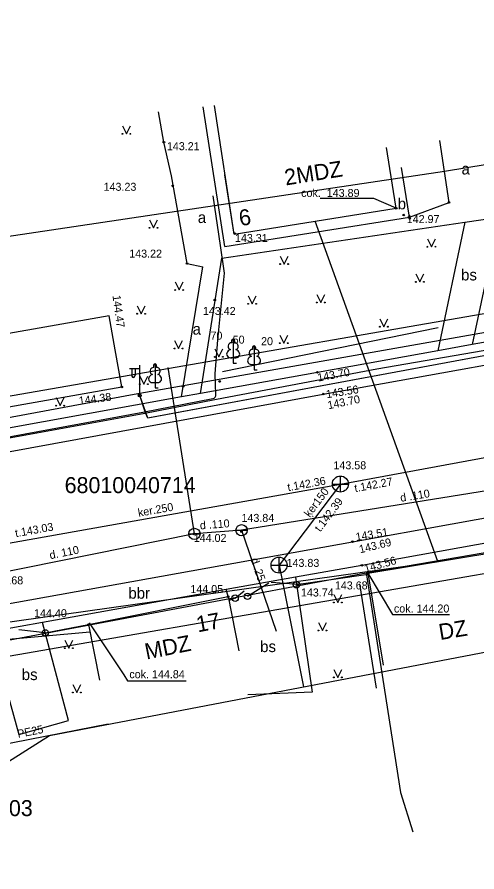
# Model space of a CAD drawing. Extents: x 728492 to 729038, y 272968 to 273171.
# Drawn here: x 728700.1 to 728728.8, y 273058.4 to 273111.8 of the extents above; entities that cross this region are included whole.
import ezdxf

# ---------------------------------------------------------------- set-up
doc = ezdxf.new("R2010")
doc.units = 0
for name, color, linetype in [('APGR_SARK_####_####_#', 7, 'Continuous'), ('APGS_ACRL_####_####_#', 7, 'Continuous'), ('APGS_ELEM_####_####_#', 7, 'Continuous'), ('APGS_VADP_ZSPR_####_I', 7, 'Continuous'), ('BUVE_BDET_####_####_#', 7, 'Continuous'), ('BUVE_BDET_####_TKST_#', 7, 'Continuous'), ('BUVE_EKAS_####_####_#', 7, 'Continuous'), ('BUVE_EKAS_ADRS_TKST_#', 7, 'Continuous'), ('BUVE_EKAS_RAKS_TKST_#', 7, 'Continuous'), ('CELI_CAPM_####_####_#', 7, 'Continuous'), ('CELI_CMAL_####_####_#', 7, 'Continuous'), ('CELI_CSEG_####_TKST_#', 7, 'Continuous'), ('CELI_SEGL_####_####_#', 7, 'Continuous'), ('ELEK_VADP_ZSPR_####_I', 7, 'Continuous'), ('NORB_ELEM_####_####_#', 7, 'Continuous'), ('NORB_ZOGS_BARJ_####_#', 7, 'Continuous'), ('NORB_ZOGS_KOKA_####_#', 7, 'Continuous'), ('RAMI_UZMR_####_####_#', 7, 'Continuous'), ('RELJ_AATZ_####_TKST_#', 7, 'Continuous'), ('RELJ_ELEM_####_####_#', 7, 'Continuous'), ('ROBZ_KADS_####_TKST_#', 7, 'Continuous'), ('ROBZ_UZMR_####_####_#', 7, 'Continuous'), ('SAKT_STUT_####_####_#', 7, 'Continuous'), ('SAKT_VADV_KLIN_####_#', 7, 'Continuous'), ('SKAN_ELEM_####_####_#', 7, 'Continuous'), ('SKAN_VADP_PAST_####_#', 7, 'Continuous'), ('SKAN_VADP_PAST_TKST_#', 7, 'Continuous'), ('TERT_DIAM_####_TKST_#', 7, 'Continuous'), ('TERT_DZOG_####_####_#', 7, 'Continuous'), ('TERT_ELEM_####_####_#', 7, 'Continuous'), ('TERT_KRND_####_####_#', 7, 'Continuous'), ('UDTK_ELEM_####_####_#', 7, 'Continuous'), ('UDTK_ELEM_####_TKST_#', 7, 'Continuous'), ('UDTK_VADP_UDEN_####_#', 7, 'Continuous'), ('UDTK_VADP_UDEN_TKST_#', 7, 'Continuous')]:
    doc.layers.add(name, color=color, linetype=linetype)

msp = doc.modelspace()

# ---------------------------------------------------------------- linework, layer by layer
at = {"layer": 'APGR_SARK_####_####_#'}
for points in [[(728813.011, 273107.831), (728678.847, 273084.513)], [(728815.186, 273091.969), (728680.999, 273068.647)]]:
    msp.add_lwpolyline(points, dxfattribs=at)
at = {"layer": 'APGS_ACRL_####_####_#'}
msp.add_lwpolyline([(728761.587, 273096.618), (728761.498, 273096.52), (728729.511, 273090.707), (728708.292, 273086.771), (728707.787, 273088.186)], dxfattribs=at)
at = {"layer": 'APGS_ELEM_####_####_#'}
for p, q in [((728707.787, 273089.853), (728707.152, 273089.848)), ((728707.287, 273089.849), (728707.287, 273089.457)), ((728707.497, 273089.851), (728707.497, 273089.457)), ((728707.787, 273088.186), (728707.787, 273090.069))]:
    msp.add_line(p, q, dxfattribs=at)
msp.add_circle((728707.787, 273088.186), 0.09, dxfattribs=at)
msp.add_ellipse((728707.392, 273089.457), major_axis=(0, 0.151), ratio=0.695971, start_param=1.570796, end_param=4.712389, dxfattribs=at)
at = {"layer": 'APGS_VADP_ZSPR_####_I'}
msp.add_lwpolyline([(728761.349, 273097.858), (728761.587, 273096.618), (728761.498, 273096.52), (728761.308, 273096.474), (728729.511, 273090.707), (728708.404, 273086.792), (728708.292, 273086.771), (728708.145, 273087.084), (728707.787, 273088.186)], dxfattribs=at)
at = {"layer": 'BUVE_BDET_####_####_#'}
for points in [[(728723.804, 273099.877), (728722.41, 273100.489), (728719.052, 273100.489)], [(728722.041, 273077.083), (728723.576, 273074.502), (728727.106, 273074.502)], [(728727.106, 273074.502), (728727.135, 273074.502)], [(728704.642, 273073.962), (728706.792, 273070.714)], [(728706.792, 273070.714), (728707.033, 273070.35), (728710.684, 273070.35)]]:
    msp.add_lwpolyline(points, dxfattribs=at)
at = {"layer": 'BUVE_EKAS_####_####_#'}
for p, q in [((728713.69, 273098.259), (728712.451, 273106.301)), ((728723.406, 273102.365), (728723.196, 273103.68)), ((728713.69, 273098.259), (728713.097, 273101.965)), ((728723.804, 273099.877), (728723.406, 273102.365)), ((728713.69, 273098.259), (728723.804, 273099.877)), ((728705.885, 273093.165), (728689.889, 273090.35)), ((728706.26, 273091.033), (728705.885, 273093.165)), ((728706.669, 273088.711), (728706.26, 273091.033)), ((728690.777, 273085.914), (728706.669, 273088.711)), ((728722.041, 273077.083), (728730.776, 273078.534)), ((728722.041, 273077.083), (728722.599, 273073.722)), ((728704.584, 273073.861), (728713.308, 273075.607)), ((728713.308, 273075.607), (728713.984, 273072.231)), ((728704.584, 273073.861), (728705.28, 273070.386)), ((728722.599, 273073.722), (728722.996, 273071.335))]:
    msp.add_line(p, q, dxfattribs=at)
at = {"layer": 'CELI_CAPM_####_####_#'}
for points in [[(728676.374, 273071.049), (728680.397, 273071.606), (728696.384, 273074.602), (728721.076, 273079.042), (728739.743, 273082.405), (728759.114, 273085.751), (728811.654, 273095.023), (728814.654, 273095.178), (728815.22, 273095.032), (728815.785, 273094.657), (728816.384, 273093.154), (728816.384, 273093.154), (728817.477, 273084.163), (728819.159, 273072.476)], [(728674.775, 273080.133), (728674.775, 273080.133), (728693.992, 273083.644), (728719.252, 273088.265), (728737.995, 273091.64)]]:
    msp.add_lwpolyline(points, dxfattribs=at)
at = {"layer": 'CELI_CMAL_####_####_#'}
for p, q in [((728713.099, 273097.487), (728711.753, 273106.221)), ((728727.102, 273100.241), (728726.526, 273104.108)), ((728724.628, 273099.331), (728724.132, 273102.433)), ((728710.744, 273096.425), (728709.771, 273101.908)), ((728713.099, 273097.487), (728724.628, 273099.331)), ((728730.227, 273099.328), (728728.55, 273091.364)), ((728712.925, 273096.75), (728728.091, 273099.006)), ((728728.091, 273099.006), (728726.401, 273090.976)), ((728711.592, 273088.304), (728712.925, 273096.75)), ((728710.393, 273088.087), (728711.732, 273096.227)), ((728710.744, 273096.425), (728711.732, 273096.227)), ((728737.596, 273092.997), (728728.55, 273091.364)), ((728726.401, 273090.976), (728718.885, 273089.62)), ((728718.885, 273089.62), (728711.592, 273088.304)), ((728710.393, 273088.087), (728693.469, 273085.032)), ((728733.529, 273079.685), (728721.657, 273077.563)), ((728721.657, 273077.563), (728717.507, 273076.822)), ((728713.195, 273076.052), (728701.721, 273074.002))]:
    msp.add_line(p, q, dxfattribs=at)
for points in [[(728710.744, 273096.425), (728709.771, 273101.908), (728709.298, 273104.007), (728708.966, 273105.9)], [(728724.628, 273099.331), (728727.102, 273100.241)], [(728717.507, 273076.822), (728718.561, 273069.642)], [(728713.308, 273075.607), (728713.195, 273076.052)], [(728698.448, 273073.418), (728700.24, 273067.002), (728703.335, 273067.866), (728701.721, 273074.002)], [(728718.561, 273069.642), (728714.535, 273069.474)]]:
    msp.add_lwpolyline(points, dxfattribs=at)
at = {"layer": 'CELI_SEGL_####_####_#'}
for p, q in [((728728.091, 273099.006), (728730.227, 273099.328)), ((728728.55, 273091.364), (728726.401, 273090.976)), ((728711.592, 273088.304), (728710.393, 273088.087)), ((728717.507, 273076.822), (728713.195, 273076.052)), ((728701.721, 273074.002), (728698.448, 273073.418))]:
    msp.add_line(p, q, dxfattribs=at)
at = {"layer": 'ELEK_VADP_ZSPR_####_I'}
for points in [[(728789.187, 273101.908), (728785.18, 273101.176), (728775.571, 273099.385), (728767.143, 273097.829), (728756.289, 273095.852), (728744.902, 273093.77), (728738.696, 273092.686), (728731.653, 273091.378), (728722.585, 273089.813), (728712.579, 273087.924)], [(728712.551, 273088.237), (728712.499, 273089.541), (728712.66, 273091.659), (728713.08, 273095.831), (728712.823, 273097.55), (728712.37, 273100.65)], [(728681.295, 273082.233), (728688.088, 273083.536), (728697.444, 273085.206), (728707.979, 273087.132), (728712.349, 273087.981)], [(728712.579, 273087.924), (728707.997, 273087.034), (728697.462, 273085.108), (728688.106, 273083.438), (728681.224, 273082.117)]]:
    msp.add_lwpolyline(points, dxfattribs=at)
msp.add_arc((728712.301, 273088.227), 0.25, 280.9945, 2.2796, dxfattribs=at)
at = {"layer": 'NORB_ELEM_####_####_#'}
for centre in [(728717.576, 273076.352), (728713.743, 273075.512), (728714.515, 273075.628), (728701.895, 273073.34)]:
    msp.add_circle(centre, 0.202, dxfattribs=at)
at = {"layer": 'NORB_ZOGS_BARJ_####_#'}
for points in [[(728714.515, 273075.628), (728715.859, 273076.48)], [(728717.7, 273076.37), (728715.992, 273076.5)], [(728713.743, 273075.512), (728714.317, 273075.963)], [(728701.895, 273073.34), (728700.246, 273073.539)]]:
    msp.add_lwpolyline(points, dxfattribs=at)
at = {"layer": 'NORB_ZOGS_KOKA_####_#'}
for points in [[(728722.055, 273077), (728717.576, 273076.352)], [(728713.743, 273075.512), (728713.354, 273075.375)], [(728701.895, 273073.34), (728704.584, 273073.861)]]:
    msp.add_lwpolyline(points, dxfattribs=at)
at = {"layer": 'RAMI_UZMR_####_####_#'}
msp.add_lwpolyline([(728688.721, 273058.407), (728702.149, 273066.922), (728733.452, 273072.937), (728813.127, 273088.247), (728815.181, 273072.879), (728831.342, 273076.994), (728831.817, 273091.35), (728930.137, 273106.573), (728962.389, 273111.567), (728966.363, 273103.835), (728988.796, 273109.153), (728985.811, 273141.417), (728955.146, 273144.603), (728957.616, 273137.975), (728904.333, 273130.641), (728847.677, 273120.095), (728823.483, 273119.793), (728790.036, 273112.558), (728726.814, 273102.175), (728686.914, 273096.216)], dxfattribs=at)
at = {"layer": 'RELJ_ELEM_####_####_#'}
for centre in [(728709.298, 273104.007), (728709.298, 273104.007), (728709.845, 273101.281), (728727.102, 273100.241), (728723.804, 273099.877), (728724.275, 273099.452), (728724.641, 273099.249), (728713.715, 273098.301), (728710.744, 273096.425), (728712.476, 273094.145), (728718.885, 273089.62), (728712.786, 273089.055), (728706.669, 273088.711), (728710.501, 273088.746), (728719.252, 273088.265), (728720.314, 273082.621), (728711.162, 273079.525), (728714.143, 273079.666), (728721.076, 273079.042), (728716.486, 273077.576), (728721.657, 273077.563), (728722.041, 273077.083), (728717.638, 273076.361), (728713.308, 273075.607), (728704.584, 273073.861)]:
    msp.add_circle(centre, 0.05, dxfattribs=at)
at = {"layer": 'ROBZ_UZMR_####_####_#'}
for p, q in [((728741.291, 273094.217), (728707.448, 273088.246)), ((728707.448, 273088.246), (728675.015, 273082.231)), ((728721.926, 273077.099), (728730.805, 273078.627)), ((728677.033, 273068.656), (728721.926, 273077.099)), ((728721.926, 273077.099), (728724.07, 273063.372)), ((728724.07, 273063.372), (728724.84, 273060.908))]:
    msp.add_line(p, q, dxfattribs=at)
at = {"layer": 'SAKT_STUT_####_####_#'}
msp.add_line((728704.68, 273073.384), (728677.472, 273070.914), dxfattribs=at)
at = {"layer": 'SAKT_VADV_KLIN_####_#'}
for points in [[(728726.409, 273077.808), (728718.747, 273099.068)], [(728677.472, 273070.914), (728725.843, 273077.714)]]:
    msp.add_lwpolyline(points, dxfattribs=at)
at = {"layer": 'SKAN_ELEM_####_####_#'}
for p, q in [((728720.316, 273082.146), (728720.316, 273083.146)), ((728719.816, 273082.646), (728720.816, 273082.646)), ((728716.486, 273077.076), (728716.486, 273078.076)), ((728715.986, 273077.576), (728716.986, 273077.576))]:
    msp.add_line(p, q, dxfattribs=at)
for centre in [(728720.316, 273082.646), (728716.486, 273077.576)]:
    msp.add_circle(centre, 0.5, dxfattribs=at)
at = {"layer": 'SKAN_VADP_PAST_####_#'}
for points in [[(728720.316, 273082.646), (728734.188, 273085.206), (728748.358, 273088.046), (728744.985, 273109.561), (728747.785, 273109.953)], [(728698.991, 273078.836), (728720.316, 273082.646), (728716.486, 273077.576), (728718.007, 273069.977)]]:
    msp.add_lwpolyline(points, dxfattribs=at)
at = {"layer": 'TERT_DZOG_####_####_#'}
msp.add_lwpolyline([(728712.953, 273089.679), (728726.428, 273092.418)], dxfattribs=at)
at = {"layer": 'TERT_ELEM_####_####_#'}
for p, q in [((728706.705, 273105.031), (728706.955, 273104.531)), ((728706.955, 273104.531), (728707.205, 273105.031)), ((728708.398, 273099.156), (728708.648, 273098.656)), ((728708.648, 273098.656), (728708.898, 273099.156)), ((728725.749, 273097.976), (728725.999, 273097.476)), ((728725.999, 273097.476), (728726.249, 273097.976)), ((728716.559, 273096.89), (728716.809, 273096.39)), ((728716.809, 273096.39), (728717.059, 273096.89)), ((728725.035, 273095.776), (728725.285, 273095.276)), ((728725.285, 273095.276), (728725.535, 273095.776)), ((728709.996, 273095.271), (728710.246, 273094.771)), ((728710.246, 273094.771), (728710.496, 273095.271)), ((728714.561, 273094.405), (728714.811, 273093.905)), ((728714.811, 273093.905), (728715.061, 273094.405)), ((728718.842, 273094.491), (728719.092, 273093.991)), ((728719.092, 273093.991), (728719.342, 273094.491)), ((728707.628, 273093.785), (728707.878, 273093.285)), ((728707.878, 273093.285), (728708.128, 273093.785)), ((728722.781, 273092.976), (728723.031, 273092.476)), ((728723.031, 273092.476), (728723.281, 273092.976)), ((728716.53, 273091.948), (728716.78, 273091.448)), ((728716.78, 273091.448), (728717.03, 273091.948)), ((728709.968, 273091.614), (728710.218, 273091.114)), ((728710.218, 273091.114), (728710.468, 273091.614)), ((728712.478, 273091.091), (728712.728, 273090.591)), ((728712.728, 273090.591), (728712.978, 273091.091)), ((728713.623, 273090.546), (728713.623, 273090.199)), ((728713.623, 273090.199), (728713.823, 273090.199)), ((728714.929, 273090.13), (728714.929, 273089.783)), ((728714.929, 273089.783), (728715.129, 273089.783)), ((728707.799, 273089.386), (728708.049, 273088.886)), ((728708.049, 273088.886), (728708.299, 273089.386)), ((728708.748, 273088.999), (728708.748, 273088.652)), ((728708.748, 273088.652), (728708.948, 273088.652)), ((728702.576, 273088.043), (728702.826, 273087.543)), ((728702.826, 273087.543), (728703.076, 273088.043)), ((728719.911, 273075.745), (728720.161, 273075.245)), ((728720.161, 273075.245), (728720.411, 273075.745)), ((728718.945, 273073.995), (728719.195, 273073.495)), ((728719.195, 273073.495), (728719.445, 273073.995)), ((728703.109, 273072.891), (728703.359, 273072.391)), ((728703.359, 273072.391), (728703.609, 273072.891)), ((728719.911, 273071.061), (728720.161, 273070.561)), ((728720.161, 273070.561), (728720.411, 273071.061)), ((728703.612, 273070.121), (728703.862, 273069.621)), ((728703.862, 273069.621), (728704.112, 273070.121))]:
    msp.add_line(p, q, dxfattribs=at)
for points in [[(728713.623, 273091.699), (728713.623, 273090.546)], [(728713.713, 273091.467), (728713.712, 273091.468)], [(728714.929, 273091.283), (728714.929, 273090.13)], [(728715.019, 273091.051), (728715.018, 273091.052)], [(728708.748, 273090.152), (728708.748, 273088.999)], [(728708.838, 273089.92), (728708.837, 273089.921)]]:
    msp.add_lwpolyline(points, dxfattribs=at)
for centre, radius in [((728706.705, 273104.53), 0.028), ((728707.205, 273104.53), 0.0263), ((728708.398, 273098.656), 0.028), ((728708.898, 273098.656), 0.0263), ((728725.748, 273097.476), 0.028), ((728726.248, 273097.476), 0.0263), ((728716.559, 273096.39), 0.028), ((728717.059, 273096.39), 0.0263), ((728725.035, 273095.276), 0.028), ((728725.535, 273095.276), 0.0263), ((728709.996, 273094.77), 0.028), ((728710.496, 273094.77), 0.0263), ((728714.561, 273093.904), 0.028), ((728715.061, 273093.904), 0.0263), ((728718.842, 273093.99), 0.028), ((728719.342, 273093.99), 0.0263), ((728707.627, 273093.285), 0.028), ((728708.127, 273093.285), 0.0263), ((728722.78, 273092.476), 0.028), ((728723.28, 273092.476), 0.0263), ((728716.53, 273091.447), 0.028), ((728717.03, 273091.447), 0.0263), ((728709.968, 273091.114), 0.028), ((728710.468, 273091.114), 0.0263), ((728712.477, 273090.59), 0.028), ((728712.977, 273090.59), 0.0263), ((728707.798, 273088.885), 0.028), ((728708.298, 273088.885), 0.0263), ((728702.576, 273087.542), 0.028), ((728703.076, 273087.542), 0.0263), ((728719.911, 273075.245), 0.028), ((728720.411, 273075.245), 0.0263), ((728718.945, 273073.495), 0.028), ((728719.445, 273073.495), 0.0263), ((728703.109, 273072.391), 0.028), ((728703.609, 273072.391), 0.0263), ((728719.911, 273070.561), 0.028), ((728720.411, 273070.561), 0.0263), ((728703.612, 273069.62), 0.028), ((728704.112, 273069.62), 0.0263)]:
    msp.add_circle(centre, radius, dxfattribs=at)
for centre, major_axis, ratio, start_param, end_param in [((728713.623, 273091.549), (0, -0.15), 0.707107, 3.14537, 5.287485), ((728713.623, 273091.549), (0, -0.15), 0.707107, 0.995701, 3.137816), ((728713.495, 273091.254), (-0.039, -0.212), 0.861323, 3.141593, 6.283185), ((728713.751, 273091.254), (0.039, -0.212), 0.861323, 0, 3.141593), ((728714.929, 273091.133), (0, -0.15), 0.707107, 3.14537, 5.287485), ((728714.929, 273091.133), (0, -0.15), 0.707107, 0.995701, 3.137816), ((728713.533, 273090.792), (0.307, 0.095), 0.814445, 1.570796, 4.752015), ((728713.713, 273090.792), (-0.307, 0.095), 0.814445, 1.531171, 4.712389), ((728714.839, 273090.376), (0.307, 0.095), 0.814445, 1.570796, 4.752015), ((728714.801, 273090.838), (-0.039, -0.212), 0.861323, 3.141593, 6.283185), ((728715.019, 273090.376), (-0.307, 0.095), 0.814445, 1.531171, 4.712389), ((728715.057, 273090.838), (0.039, -0.212), 0.861323, 0, 3.141593), ((728708.748, 273090.002), (0, -0.15), 0.707107, 3.14537, 5.287485), ((728708.748, 273090.002), (0, -0.15), 0.707107, 0.995701, 3.137816), ((728708.62, 273089.707), (-0.039, -0.212), 0.861323, 3.141593, 6.283185), ((728708.876, 273089.707), (0.039, -0.212), 0.861323, 0, 3.141593), ((728708.658, 273089.245), (0.307, 0.095), 0.814445, 1.570796, 4.752015), ((728708.838, 273089.245), (-0.307, 0.095), 0.814445, 1.531171, 4.712389)]:
    msp.add_ellipse(centre, major_axis=major_axis, ratio=ratio, start_param=start_param, end_param=end_param, dxfattribs=at)
at = {"layer": 'TERT_KRND_####_####_#'}
msp.add_lwpolyline([(728721.515, 273076.413), (728722.55, 273069.88)], dxfattribs=at)
at = {"layer": 'UDTK_ELEM_####_####_#'}
for p, q in [((728710.853, 273079.532), (728711.555, 273079.532)), ((728711.203, 273079.532), (728711.203, 273079.533)), ((728713.797, 273079.76), (728714.499, 273079.76)), ((728714.147, 273079.76), (728714.147, 273079.761))]:
    msp.add_line(p, q, dxfattribs=at)
for centre in [(728714.148, 273079.76), (728711.204, 273079.532)]:
    msp.add_circle(centre, 0.351, dxfattribs=at)
at = {"layer": 'UDTK_VADP_UDEN_####_#'}
for p, q in [((728711.204, 273079.532), (728709.57, 273089.922)), ((728732.933, 273082.788), (728714.148, 273079.76)), ((728714.148, 273079.76), (728716.304, 273073.453)), ((728705.829, 273067.642), (728698.468, 273066.202))]:
    msp.add_line(p, q, dxfattribs=at)
msp.add_lwpolyline([(728714.148, 273079.76), (728711.204, 273079.532), (728698.512, 273076.977)], dxfattribs=at)

# ---------------------------------------------------------------- texts
at = {"layer": 'BUVE_BDET_####_TKST_#'}
for s, p in [('cok.  143.89', (728717.87, 273100.584)), ('cok. 144.20', (728723.662, 273074.616)), ('cok. 144.84', (728707.143, 273070.51))]:
    msp.add_text(s, height=0.49999, dxfattribs=at).set_placement(p)
at = {"layer": 'BUVE_EKAS_ADRS_TKST_#'}
for s, rotation, p in [('6', 9.089, (728714.066, 273098.758)), ('17', 10.658, (728711.419, 273073.374))]:
    msp.add_text(s, height=1, rotation=rotation, dxfattribs=at).set_placement(p)
at = {"layer": 'BUVE_EKAS_RAKS_TKST_#'}
for s, rotation, p in [('2MDZ', 9.089, (728716.913, 273101.3)), ('DZ', 9.431, (728726.545, 273072.893)), ('MDZ', 11.318, (728708.213, 273071.675))]:
    msp.add_text(s, height=1, rotation=rotation, dxfattribs=at).set_placement(p)
at = {"layer": 'CELI_CSEG_####_TKST_#'}
for s, p in [('a', (728727.881, 273101.99)), ('b', (728723.898, 273099.811)), ('a', (728711.415, 273098.955)), ('bs', (728727.854, 273095.368)), ('a', (728711.092, 273091.981)), ('bbr', (728707.083, 273075.479)), ('bs', (728715.308, 273072.142)), ('bs', (728700.422, 273070.393))]:
    msp.add_text(s, height=0.7, dxfattribs=at).set_placement(p)
at = {"layer": 'RELJ_AATZ_####_TKST_#'}
for s, p in [(' 143.21', (728709.298, 273103.507)), (' 143.23', (728705.347, 273100.97)), (' 142.97', (728724.275, 273098.952)), (' 143.31', (728713.552, 273097.77)), (' 143.22', (728706.949, 273096.794)), (' 143.42', (728711.547, 273093.21)), (' 144.05', (728710.767, 273075.833)), ('143.68', (728719.974, 273076.059)), (' 143.74', (728717.67, 273075.618)), (' 144.40', (728701.007, 273074.324))]:
    msp.add_text(s, height=0.5, dxfattribs=at).set_placement(p)
for s, rotation, p in [(' 144.47', 277.7369, (728706.064, 273094.598)), ('143.70', 10.3842, (728718.934, 273089.046)), ('143.56', 9.2458, (728719.466, 273088.002)), (' 144.38', 7.5673, (728703.834, 273087.569)), ('143.70', 11.643, (728719.576, 273087.314)), ('143.51', 9.2801, (728721.313, 273079.09)), ('143.69', 13.7178, (728721.554, 273078.313)), (' 143.56', 15.3737, (728721.699, 273077.062))]:
    msp.add_text(s, height=0.5, rotation=rotation, dxfattribs=at).set_placement(p)
at = {"layer": 'ROBZ_KADS_####_TKST_#'}
for s, p in [('68010040714', (728703.101, 273082.077)), ('68010040003', (728692.929, 273061.893))]:
    msp.add_text(s, height=1, dxfattribs=at).set_placement(p)
at = {"layer": 'SKAN_ELEM_####_####_#'}
for s, p in [('143.58', (728719.885, 273083.567)), ('143.83', (728716.958, 273077.467))]:
    msp.add_text(s, height=0.5, dxfattribs=at).set_placement(p)
at = {"layer": 'SKAN_VADP_PAST_TKST_#'}
for s, rotation, p in [('t.142.36', 10.13, (728717.055, 273082.194)), ('t.142.27', 10.456, (728721.239, 273082.134)), ('ķer150', 52.932, (728718.406, 273080.529)), ('t.142.39', 52.932, (728719.058, 273079.621)), ('ker.250', 10.13, (728707.725, 273080.595)), ('t.143.03', 10.13, (728700.052, 273079.322))]:
    msp.add_text(s, height=0.5, rotation=rotation, dxfattribs=at).set_placement(p)
at = {"layer": 'TERT_DIAM_####_TKST_#'}
for s, p in [('70', (728712.207, 273091.67)), (' 50', (728713.408, 273091.418)), ('20', (728715.366, 273091.321))]:
    msp.add_text(s, height=0.5, dxfattribs=at).set_placement(p)
at = {"layer": 'UDTK_ELEM_####_TKST_#'}
for s, p in [('143.84', (728714.143, 273080.278)), ('144.02', (728711.162, 273079.025)), ('144.68', (728698.468, 273076.376))]:
    msp.add_text(s, height=0.5, dxfattribs=at).set_placement(p)
at = {"layer": 'UDTK_VADP_UDEN_TKST_#'}
for s, rotation, p in [('d .110', 9.1569, (728724.095, 273081.533)), ('d .110', 4.4285, (728711.564, 273079.806)), ('d. 110', 11.382, (728702.209, 273077.944)), ('d .25', 288.87, (728714.703, 273077.936)), ('PE25', 11.073, (728700.199, 273066.78))]:
    msp.add_text(s, height=0.5, rotation=rotation, dxfattribs=at).set_placement(p)

doc.saveas('drawing.dxf')
